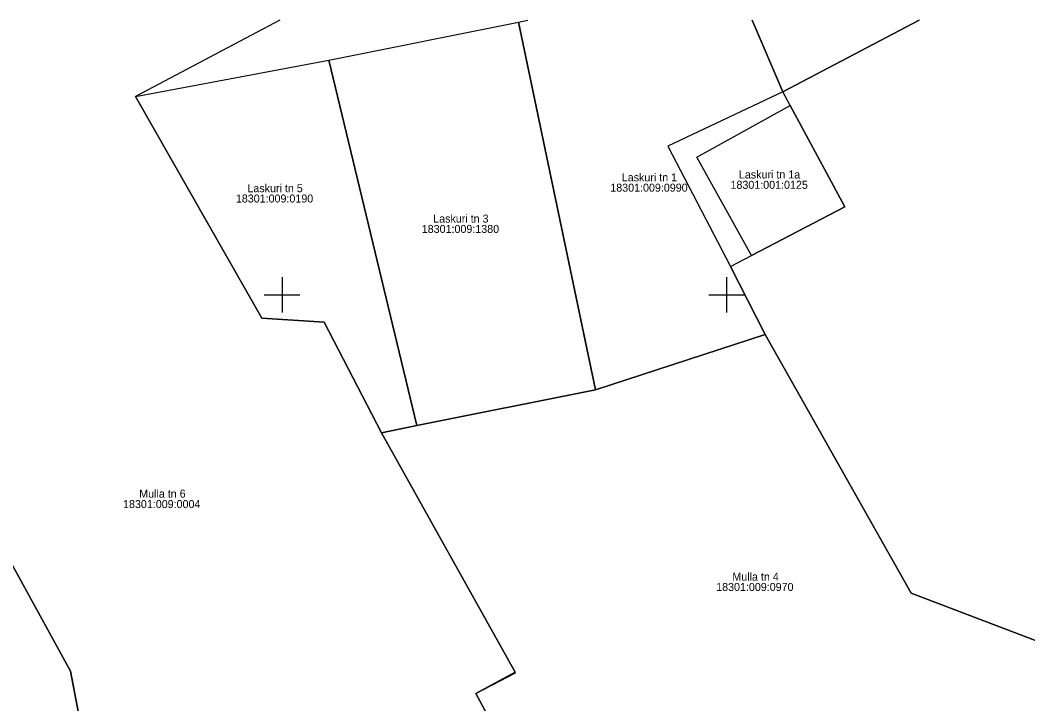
# Model space of a CAD drawing. Extents: x 473307 to 473719, y 6532843 to 6533381.
# Drawn here: x 473420.5 to 473533.9, y 6533304 to 6533380.9 of the extents above; entities that cross this region are included whole.
import ezdxf

# ---------------------------------------------------------------- set-up
doc = ezdxf.new("R2010")
doc.units = 0
for name, color, linetype in [('Default', 7, 'Continuous'), ('PIIR', 7, 'Continuous'), ('VORK', 7, 'Continuous')]:
    doc.layers.add(name, color=color, linetype=linetype)

# ---------------------------------------------------------------- blocks, each defined once
blk = doc.blocks.new('VKORIS')
at = {"layer": 'Default'}
for p, q in [((0, 4), (0, -4)), ((-4, 0), (4, 0))]:
    blk.add_line(p, q, dxfattribs=at)

msp = doc.modelspace()

# ---------------------------------------------------------------- linework, layer by layer
at = {"layer": 'PIIR'}
for points in [[(473449.76, 6533380.88), (473433.52, 6533372.29), (473447.71, 6533347.37), (473454.72, 6533346.94), (473461.17, 6533334.49), (473476.21, 6533307.58), (473471.79, 6533305.18), (473480.69, 6533288.74), (473430.17, 6533286.8), (473426.19, 6533307.67), (473415.91, 6533326.36), (473400.95, 6533323.6), (473392.61, 6533364.11), (473394.06, 6533370.53), (473399.03, 6533371.95), (473403.75, 6533374.68), (473415.38, 6533380.88)], [(473502.89, 6533380.88), (473506.33, 6533372.83), (473493.39, 6533366.71), (473500.43, 6533353.19), (473504.35, 6533345.55), (473485.24, 6533339.32), (473476.59, 6533380.67), (473477.66, 6533380.88)], [(473546.85, 6533380.88), (473548.67, 6533377.72), (473552.06, 6533377.52), (473554.47, 6533373.83), (473554.77, 6533368.87), (473546.99, 6533364.16), (473553.35, 6533352.46), (473569.29, 6533323.48), (473585.1, 6533294.7), (473545.58, 6533292.4), (473536.31, 6533310.52), (473520.75, 6533316.46), (473504.35, 6533345.55), (473500.43, 6533353.19), (473502.79, 6533354.42), (473513.31, 6533359.89), (473507.16, 6533371.28), (473506.33, 6533372.83), (473521.65, 6533380.88)], [(473521.65, 6533380.88), (473506.33, 6533372.83), (473502.89, 6533380.88)]]:
    msp.add_lwpolyline(points, dxfattribs=at)
for points in [[(473465.17, 6533335.3), (473455.26, 6533376.4), (473476.59, 6533380.67), (473485.24, 6533339.32)], [(473433.52, 6533372.29), (473455.26, 6533376.4), (473465.17, 6533335.3), (473461.17, 6533334.49), (473454.72, 6533346.94), (473447.71, 6533347.37)], [(473496.66, 6533365.48), (473507.16, 6533371.28), (473513.31, 6533359.89), (473502.79, 6533354.42)], [(473480.69, 6533288.74), (473471.79, 6533305.18), (473476.25, 6533307.51), (473476.21, 6533307.58), (473461.17, 6533334.49), (473465.17, 6533335.3), (473485.24, 6533339.32), (473504.35, 6533345.55), (473520.75, 6533316.46), (473536.31, 6533310.52), (473545.58, 6533292.4), (473480.73, 6533288.66)], [(473400.95, 6533323.6), (473415.91, 6533326.36), (473426.19, 6533307.67), (473429.73, 6533289.19), (473409.45, 6533285.94)]]:
    msp.add_lwpolyline(points, close=True, dxfattribs=at)

# ---------------------------------------------------------------- block references
at = {"layer": 'VORK', "xscale": 0.5, "yscale": 0.5}
for p in [(473450, 6533350), (473500, 6533350)]:
    msp.add_blockref('VKORIS', p, dxfattribs=at)

# ---------------------------------------------------------------- texts
at = {"layer": 'PIIR'}
for s, p in [('Laskuri tn 1', (473488.21, 6533362.76)), ('Laskuri tn 1a', (473501.39, 6533363.08)), ('18301:001:0125', (473500.44, 6533361.92)), ('Laskuri tn 5', (473446.1, 6533361.54)), ('18301:009:0990', (473486.92, 6533361.6)), ('18301:009:0190', (473444.8, 6533360.38)), ('Laskuri tn 3', (473467, 6533358.12)), ('18301:009:1380', (473465.71, 6533356.96)), ('Mulla tn 6', (473433.93, 6533327.19)), ('18301:009:0004', (473432.11, 6533326.02)), ('Mulla tn 4', (473500.65, 6533317.86)), ('18301:009:0970', (473498.83, 6533316.7))]:
    msp.add_text(s, height=0.9, dxfattribs=at).set_placement(p)

doc.saveas('drawing.dxf')
